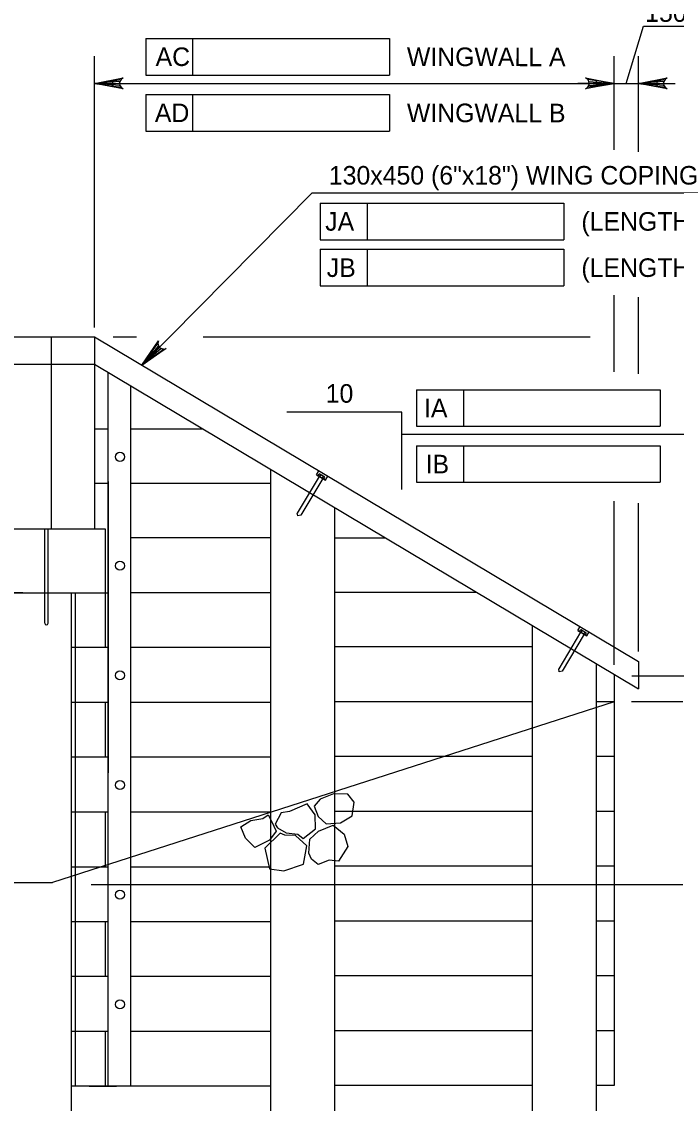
# Model space of a CAD drawing. Extents: x 635440 to 640306, y 296653 to 298484.
# Drawn here: x 638830 to 638935.8, y 296754 to 296928.7 of the extents above; entities that cross this region are included whole.
import ezdxf

# ---------------------------------------------------------------- set-up
doc = ezdxf.new("R2010")
doc.units = 0
doc.layers.add('4', color=7, linetype='Continuous')
doc.layers.add('5', color=7, linetype='Continuous')

# ---------------------------------------------------------------- blocks, each defined once
blk = doc.blocks.new('ROCK')
at = {"layer": '4'}
for points in [[(2.36725, 1.088), (2.2065, 0.82625), (2.378625, 0.506625), (2.66975, 0.3095), (3.128875, 0.403375), (3.48475, 0.6775), (3.4915, 1.123375), (3.25625, 1.36725), (2.783625, 1.308375)], [(1.10175, -0.02725), (1.4015, -0.159125), (1.78825, -0.148875), (1.980875, -0.266), (2.343375, 0.09475), (2.27875, 0.5505), (1.969375, 0.883), (1.4225, 0.553625), (1.152875, 0.479), (1.0105, 0.082)], [(0.74675, 0.359875), (0.882, 0.16), (1.072875, -0.144), (0.892, -0.457375), (0.448125, -0.758625), (0.1, -0.49325), (-0.095, -0.146375), (0.202875, 0.1025), (0.579125, 0.219875)], [(2.231375, -0.71725), (2.2025, -0.266375), (2.45475, 0.037125), (2.9085, 0.28875), (3.2995, 0.047625), (3.46875, -0.344), (3.231625, -0.855), (2.92, -0.860375), (2.5765, -1.054625), (2.340375, -0.904375)], [(1.2085, -0.192875), (0.778375, -0.737625), (1.008375, -1.391375), (1.48725, -1.396875), (2.09825, -1.106625), (2.133375, -0.486375), (1.723125, -0.203375), (1.37425, -0.239875)]]:
    blk.add_lwpolyline(points, close=True, dxfattribs=at)

msp = doc.modelspace()

# ---------------------------------------------------------------- linework, layer by layer
at = {"layer": '4'}
for p, q in [((638812.82, 296877.78), (638841.71, 296877.78)), ((638834.73, 296877.78), (638834.73, 296873.35)), ((638841.71, 296877.78), (638929.64, 296825.35)), ((638841.71, 296877.78), (638841.71, 296873.35)), ((638795.82, 296873.35), (638841.71, 296873.35)), ((638834.73, 296873.35), (638834.73, 296846.77)), ((638841.71, 296873.35), (638929.64, 296820.92)), ((638841.71, 296873.35), (638841.71, 296846.77)), ((638843.96, 296792.52), (638843.96, 296872.01)), ((638847.59, 296793.69), (638847.59, 296869.84)), ((638843.96, 296862.88), (638841.71, 296862.88)), ((638859.28, 296862.88), (638847.59, 296862.88)), ((638870.19, 296856.37), (638870.19, 296799.56)), ((638878.04, 296855.25), (638874.5, 296849.32)), ((638878.61, 296854.91), (638875.07, 296848.98)), ((638877.6, 296855.51), (638877.98, 296856.15)), ((638877.6, 296855.51), (638879.04, 296854.65)), ((638877.87, 296855.35), (638878.02, 296855.61)), ((638878.78, 296854.81), (638877.87, 296855.35)), ((638878.24, 296855.48), (638878.09, 296855.22)), ((638878.18, 296855.63), (638878.87, 296855.22)), ((638878.21, 296855.61), (638878.21, 296855.61)), ((638878.22, 296855.6), (638878.22, 296855.6)), ((638878.23, 296855.6), (638878.23, 296855.6)), ((638878.23, 296855.58), (638878.23, 296855.58)), ((638878.24, 296855.59), (638878.24, 296855.59)), ((638878.24, 296855.57), (638878.24, 296855.57)), ((638878.24, 296855.55), (638878.24, 296855.55)), ((638878.25, 296855.53), (638878.25, 296855.53)), ((638878.25, 296855.51), (638878.25, 296855.51)), ((638878.25, 296855.5), (638878.25, 296855.5)), ((638878.25, 296855.5), (638878.25, 296855.5)), ((638878.26, 296855.58), (638878.26, 296855.58)), ((638878.26, 296855.56), (638878.26, 296855.56)), ((638878.26, 296855.55), (638878.26, 296855.55)), ((638878.27, 296855.57), (638878.27, 296855.57)), ((638878.27, 296855.56), (638878.27, 296855.56)), ((638878.27, 296855.54), (638878.27, 296855.54)), ((638878.27, 296855.52), (638878.27, 296855.52)), ((638878.27, 296855.52), (638878.27, 296855.52)), ((638878.27, 296855.51), (638878.27, 296855.51)), ((638878.27, 296855.49), (638878.27, 296855.49)), ((638878.28, 296855.56), (638878.28, 296855.56)), ((638878.28, 296855.55), (638878.28, 296855.55)), ((638878.28, 296855.55), (638878.28, 296855.55)), ((638878.28, 296855.53), (638878.28, 296855.53)), ((638878.28, 296855.51), (638878.28, 296855.51)), ((638878.28, 296855.5), (638878.28, 296855.5)), ((638878.29, 296855.52), (638878.29, 296855.52)), ((638878.29, 296855.51), (638878.29, 296855.51)), ((638878.29, 296855.49), (638878.29, 296855.49)), ((638878.3, 296855.56), (638878.3, 296855.56)), ((638878.3, 296855.54), (638878.3, 296855.54)), ((638878.31, 296855.55), (638878.31, 296855.55)), ((638878.31, 296855.53), (638878.31, 296855.53)), ((638878.31, 296855.51), (638878.31, 296855.51)), ((638878.31, 296855.5), (638878.31, 296855.5)), ((638878.32, 296855.54), (638878.32, 296855.54)), ((638878.32, 296855.53), (638878.32, 296855.53)), ((638878.32, 296855.51), (638878.32, 296855.51)), ((638878.32, 296855.49), (638878.32, 296855.49)), ((638878.33, 296855.52), (638878.33, 296855.52)), ((638878.33, 296855.5), (638878.33, 296855.5)), ((638878.34, 296855.53), (638878.34, 296855.53)), ((638878.35, 296855.53), (638878.35, 296855.53)), ((638878.35, 296855.51), (638878.35, 296855.51)), ((638878.35, 296855.49), (638878.35, 296855.49)), ((638878.36, 296855.52), (638878.36, 296855.52)), ((638878.36, 296855.5), (638878.36, 296855.5)), ((638878.36, 296855.49), (638878.36, 296855.49)), ((638878.37, 296855.51), (638878.37, 296855.51)), ((638878.37, 296855.49), (638878.37, 296855.49)), ((638878.39, 296855.5), (638878.39, 296855.5)), ((638878.39, 296855.49), (638878.39, 296855.49)), ((638878.4, 296855.5), (638878.4, 296855.5)), ((638878.4, 296855.48), (638878.4, 296855.48)), ((638878.41, 296855.49), (638878.41, 296855.49)), ((638878.42, 296855.48), (638878.42, 296855.48)), ((638878.44, 296855.47), (638878.44, 296855.47)), ((638878.45, 296855.46), (638878.45, 296855.46)), ((638878.46, 296855.46), (638878.46, 296855.46)), ((638878.7, 296855.21), (638878.54, 296854.95)), ((638878.58, 296855.39), (638878.58, 296855.39)), ((638878.59, 296855.38), (638878.59, 296855.38)), ((638878.6, 296855.38), (638878.6, 296855.38)), ((638878.62, 296855.37), (638878.62, 296855.37)), ((638878.63, 296855.36), (638878.63, 296855.36)), ((638878.63, 296855.34), (638878.63, 296855.34)), ((638878.64, 296855.35), (638878.64, 296855.35)), ((638878.64, 296855.34), (638878.64, 296855.34)), ((638878.65, 296855.34), (638878.65, 296855.34)), ((638878.65, 296855.33), (638878.65, 296855.33)), ((638878.65, 296855.31), (638878.65, 296855.31)), ((638878.66, 296855.32), (638878.66, 296855.32)), ((638878.66, 296855.3), (638878.66, 296855.3)), ((638878.67, 296855.34), (638878.67, 296855.34)), ((638878.67, 296855.28), (638878.67, 296855.28)), ((638878.68, 296855.33), (638878.68, 296855.33)), ((638878.68, 296855.31), (638878.68, 296855.31)), ((638878.68, 296855.3), (638878.68, 296855.3)), ((638878.69, 296855.32), (638878.69, 296855.32)), ((638878.69, 296855.3), (638878.69, 296855.3)), ((638878.69, 296855.29), (638878.69, 296855.29)), ((638878.69, 296855.27), (638878.69, 296855.27)), ((638878.69, 296855.26), (638878.69, 296855.26)), ((638878.7, 296855.31), (638878.7, 296855.31)), ((638878.7, 296855.3), (638878.7, 296855.3)), ((638878.7, 296855.28), (638878.7, 296855.28)), ((638878.7, 296855.26), (638878.7, 296855.26)), ((638878.7, 296855.25), (638878.7, 296855.25)), ((638878.7, 296855.23), (638878.7, 296855.23)), ((638878.71, 296855.27), (638878.71, 296855.27)), ((638878.71, 296855.26), (638878.71, 296855.26)), ((638878.71, 296855.24), (638878.71, 296855.24)), ((638878.71, 296855.22), (638878.71, 296855.22)), ((638878.72, 296855.31), (638878.72, 296855.31)), ((638878.72, 296855.29), (638878.72, 296855.29)), ((638878.72, 296855.23), (638878.72, 296855.23)), ((638878.73, 296855.3), (638878.73, 296855.3)), ((638878.73, 296855.28), (638878.73, 296855.28)), ((638878.73, 296855.27), (638878.73, 296855.27)), ((638878.73, 296855.25), (638878.73, 296855.25)), ((638878.74, 296855.29), (638878.74, 296855.29)), ((638878.74, 296855.28), (638878.74, 296855.28)), ((638878.74, 296855.26), (638878.74, 296855.26)), ((638878.74, 296855.24), (638878.74, 296855.24)), ((638878.75, 296855.27), (638878.75, 296855.27)), ((638878.75, 296855.25), (638878.75, 296855.25)), ((638878.76, 296855.28), (638878.76, 296855.28)), ((638878.77, 296855.28), (638878.77, 296855.28)), ((638878.77, 296855.26), (638878.77, 296855.26)), ((638878.77, 296855.24), (638878.77, 296855.24)), ((638878.78, 296855.27), (638878.78, 296855.27)), ((638878.78, 296855.25), (638878.78, 296855.25)), ((638878.78, 296854.81), (638878.94, 296855.07)), ((638878.79, 296855.26), (638878.79, 296855.26)), ((638878.79, 296855.24), (638878.79, 296855.24)), ((638878.81, 296855.25), (638878.81, 296855.25)), ((638878.82, 296855.25), (638878.82, 296855.25)), ((638878.83, 296855.24), (638878.83, 296855.24)), ((638879.04, 296854.65), (638879.42, 296855.29)), ((638843.96, 296854.09), (638841.71, 296854.09)), ((638870.19, 296854.09), (638847.59, 296854.09)), ((638880.53, 296850.21), (638880.53, 296804.3)), ((638874.6, 296848.88), (638874.5, 296849.32)), ((638875.07, 296848.98), (638874.6, 296848.88)), ((638792.85, 296846.77), (638843.44, 296846.77)), ((638833.7, 296831.51), (638833.7, 296846.77)), ((638834.25, 296831.51), (638834.25, 296846.77)), ((638843.44, 296846.77), (638843.44, 296827.58)), ((638870.19, 296845.3), (638847.59, 296845.3)), ((638888.79, 296845.28), (638880.53, 296845.28)), ((638880.53, 296839.01), (638880.53, 296834.32)), ((638794.4, 296836.44), (638843.96, 296836.44)), ((638830.14, 296836.44), (638826.58, 296836.44)), ((638837.99, 296836.44), (638837.99, 296791.02)), ((638838.61, 296836.44), (638838.61, 296756.71)), ((638870.19, 296836.44), (638847.59, 296836.44)), ((638903.53, 296836.49), (638880.53, 296836.49)), ((638912.45, 296831.17), (638912.45, 296814.56)), ((638919.84, 296830.33), (638920.22, 296830.97)), ((638920.11, 296830.17), (638920.27, 296830.43)), ((638920.42, 296830.45), (638921.11, 296830.03)), ((638920.45, 296830.42), (638920.45, 296830.42)), ((638920.46, 296830.42), (638920.46, 296830.42)), ((638920.47, 296830.41), (638920.47, 296830.41)), ((638920.47, 296830.39), (638920.47, 296830.39)), ((638920.48, 296830.37), (638920.48, 296830.37)), ((638920.49, 296830.4), (638920.49, 296830.4)), ((638920.49, 296830.38), (638920.49, 296830.38)), ((638920.5, 296830.39), (638920.5, 296830.39)), ((638920.5, 296830.38), (638920.5, 296830.38)), ((638920.5, 296830.36), (638920.5, 296830.36)), ((638920.51, 296830.39), (638920.51, 296830.39)), ((638920.51, 296830.37), (638920.51, 296830.37)), ((638920.51, 296830.35), (638920.51, 296830.35)), ((638920.52, 296830.38), (638920.52, 296830.38)), ((638920.52, 296830.36), (638920.52, 296830.36)), ((638920.53, 296830.36), (638920.53, 296830.36)), ((638920.54, 296830.37), (638920.54, 296830.37)), ((638920.54, 296830.35), (638920.54, 296830.35)), ((638920.55, 296830.36), (638920.55, 296830.36)), ((638920.57, 296830.36), (638920.57, 296830.36)), ((638920.28, 296830.06), (638916.75, 296824.13)), ((638920.85, 296829.73), (638917.31, 296823.79)), ((638919.84, 296830.33), (638921.28, 296829.47)), ((638921.02, 296829.62), (638920.11, 296830.17)), ((638920.49, 296830.3), (638920.33, 296830.03)), ((638920.49, 296830.33), (638920.49, 296830.33)), ((638920.49, 296830.31), (638920.49, 296830.31)), ((638920.49, 296830.31), (638920.49, 296830.31)), ((638920.5, 296830.34), (638920.5, 296830.34)), ((638920.51, 296830.34), (638920.51, 296830.34)), ((638920.51, 296830.33), (638920.51, 296830.33)), ((638920.51, 296830.32), (638920.51, 296830.32)), ((638920.51, 296830.3), (638920.51, 296830.3)), ((638920.52, 296830.34), (638920.52, 296830.34)), ((638920.52, 296830.33), (638920.52, 296830.33)), ((638920.52, 296830.31), (638920.52, 296830.31)), ((638920.53, 296830.3), (638920.53, 296830.3)), ((638920.54, 296830.34), (638920.54, 296830.34)), ((638920.54, 296830.32), (638920.54, 296830.32)), ((638920.55, 296830.34), (638920.55, 296830.34)), ((638920.55, 296830.33), (638920.55, 296830.33)), ((638920.55, 296830.31), (638920.55, 296830.31)), ((638920.56, 296830.34), (638920.56, 296830.34)), ((638920.56, 296830.32), (638920.56, 296830.32)), ((638920.56, 296830.31), (638920.56, 296830.31)), ((638920.57, 296830.31), (638920.57, 296830.31)), ((638920.58, 296830.35), (638920.58, 296830.35)), ((638920.58, 296830.33), (638920.58, 296830.33)), ((638920.59, 296830.34), (638920.59, 296830.34)), ((638920.59, 296830.32), (638920.59, 296830.32)), ((638920.59, 296830.31), (638920.59, 296830.31)), ((638920.6, 296830.33), (638920.6, 296830.33)), ((638920.6, 296830.32), (638920.6, 296830.32)), ((638920.6, 296830.3), (638920.6, 296830.3)), ((638920.61, 296830.31), (638920.61, 296830.31)), ((638920.62, 296830.32), (638920.62, 296830.32)), ((638920.63, 296830.32), (638920.63, 296830.32)), ((638920.63, 296830.3), (638920.63, 296830.3)), ((638920.64, 296830.31), (638920.64, 296830.31)), ((638920.64, 296830.29), (638920.64, 296830.29)), ((638920.65, 296830.3), (638920.65, 296830.3)), ((638920.67, 296830.29), (638920.67, 296830.29)), ((638920.68, 296830.29), (638920.68, 296830.29)), ((638920.69, 296830.28), (638920.69, 296830.28)), ((638920.71, 296830.27), (638920.71, 296830.27)), ((638920.94, 296830.02), (638920.79, 296829.76)), ((638920.82, 296830.2), (638920.82, 296830.2)), ((638920.83, 296830.2), (638920.83, 296830.2)), ((638920.84, 296830.19), (638920.84, 296830.19)), ((638920.86, 296830.18), (638920.86, 296830.18)), ((638920.87, 296830.17), (638920.87, 296830.17)), ((638920.87, 296830.16), (638920.87, 296830.16)), ((638920.88, 296830.17), (638920.88, 296830.17)), ((638920.88, 296830.15), (638920.88, 296830.15)), ((638920.89, 296830.16), (638920.89, 296830.16)), ((638920.89, 296830.14), (638920.89, 296830.14)), ((638920.89, 296830.12), (638920.89, 296830.12)), ((638920.91, 296830.15), (638920.91, 296830.15)), ((638920.91, 296830.13), (638920.91, 296830.13)), ((638920.91, 296830.12), (638920.91, 296830.12)), ((638920.92, 296830.14), (638920.92, 296830.14)), ((638920.92, 296830.13), (638920.92, 296830.13)), ((638920.92, 296830.11), (638920.92, 296830.11)), ((638920.92, 296830.09), (638920.92, 296830.09)), ((638920.93, 296830.13), (638920.93, 296830.13)), ((638920.93, 296830.12), (638920.93, 296830.12)), ((638920.93, 296830.1), (638920.93, 296830.1)), ((638920.93, 296830.08), (638920.93, 296830.08)), ((638920.93, 296830.07), (638920.93, 296830.07)), ((638920.94, 296830.13), (638920.94, 296830.13)), ((638920.94, 296830.11), (638920.94, 296830.11)), ((638920.94, 296830.09), (638920.94, 296830.09)), ((638920.94, 296830.08), (638920.94, 296830.08)), ((638920.94, 296830.06), (638920.94, 296830.06)), ((638920.94, 296830.04), (638920.94, 296830.04)), ((638920.95, 296830.07), (638920.95, 296830.07)), ((638920.95, 296830.06), (638920.95, 296830.06)), ((638920.95, 296830.04), (638920.95, 296830.04)), ((638920.96, 296830.12), (638920.96, 296830.12)), ((638920.96, 296830.1), (638920.96, 296830.1)), ((638920.96, 296830.09), (638920.96, 296830.09)), ((638920.97, 296830.11), (638920.97, 296830.11)), ((638920.97, 296830.1), (638920.97, 296830.1)), ((638920.97, 296830.08), (638920.97, 296830.08)), ((638920.97, 296830.06), (638920.97, 296830.06)), ((638920.97, 296830.05), (638920.97, 296830.05)), ((638920.98, 296830.11), (638920.98, 296830.11)), ((638920.98, 296830.09), (638920.98, 296830.09)), ((638920.98, 296830.07), (638920.98, 296830.07)), ((638920.98, 296830.06), (638920.98, 296830.06)), ((638920.99, 296830.08), (638920.99, 296830.08)), ((638920.99, 296830.06), (638920.99, 296830.06)), ((638921, 296830.1), (638921, 296830.1)), ((638921.01, 296830.09), (638921.01, 296830.09)), ((638921.01, 296830.07), (638921.01, 296830.07)), ((638921.01, 296830.06), (638921.01, 296830.06)), ((638921.02, 296830.08), (638921.02, 296830.08)), ((638921.02, 296830.07), (638921.02, 296830.07)), ((638921.02, 296829.62), (638921.18, 296829.88)), ((638921.03, 296830.07), (638921.03, 296830.07)), ((638921.03, 296830.06), (638921.03, 296830.06)), ((638921.05, 296830.07), (638921.05, 296830.07)), ((638921.06, 296830.06), (638921.06, 296830.06)), ((638921.07, 296830.05), (638921.07, 296830.05)), ((638921.28, 296829.47), (638921.66, 296830.11)), ((638843.96, 296827.58), (638837.99, 296827.58)), ((638870.19, 296827.58), (638847.59, 296827.58)), ((638912.45, 296827.7), (638880.53, 296827.7)), ((638929.64, 296825.35), (638929.64, 296820.92)), ((638916.84, 296823.69), (638916.75, 296824.13)), ((638917.31, 296823.79), (638916.84, 296823.69)), ((638922.79, 296825.01), (638922.79, 296817.94)), ((638925.74, 296823.25), (638925.74, 296818.84)), ((638925.74, 296818.84), (638834.94, 296789.62)), ((638843.96, 296818.72), (638837.99, 296818.72)), ((638843.44, 296818.72), (638843.44, 296809.86)), ((638870.19, 296818.72), (638847.59, 296818.72)), ((638912.45, 296818.84), (638880.53, 296818.84)), ((638925.74, 296818.84), (638922.79, 296818.84)), ((638925.74, 296818.84), (638925.74, 296756.83)), ((638922.79, 296818), (638922.79, 296745.37)), ((638912.45, 296814.56), (638912.45, 296745.09)), ((638843.96, 296809.86), (638837.99, 296809.86)), ((638870.19, 296809.86), (638847.59, 296809.86)), ((638898.21, 296809.98), (638880.53, 296809.98)), ((638912.45, 296809.98), (638898.21, 296809.98)), ((638925.74, 296809.98), (638922.79, 296809.98)), ((638880.53, 296804.3), (638880.53, 296745.37)), ((638843.96, 296801), (638837.99, 296801)), ((638843.44, 296801), (638843.44, 296792.14)), ((638870.19, 296801), (638847.59, 296801)), ((638912.45, 296801.12), (638880.53, 296801.12)), ((638925.74, 296801.12), (638922.79, 296801.12)), ((638870.19, 296799.56), (638870.19, 296745.09)), ((638847.59, 296756.71), (638847.59, 296793.69)), ((638843.96, 296792.14), (638837.99, 296792.14)), ((638843.96, 296756.71), (638843.96, 296792.52)), ((638870.19, 296792.14), (638847.59, 296792.14)), ((638912.45, 296792.26), (638880.53, 296792.26)), ((638925.74, 296792.26), (638922.79, 296792.26)), ((638837.99, 296791.02), (638837.99, 296745.25)), ((638805.45, 296789.62), (638834.94, 296789.62)), ((638843.96, 296783.28), (638837.99, 296783.28)), ((638843.44, 296783.28), (638843.44, 296774.43)), ((638870.19, 296783.28), (638847.59, 296783.28)), ((638912.45, 296783.41), (638880.53, 296783.41)), ((638925.74, 296783.41), (638922.79, 296783.41)), ((638843.96, 296774.43), (638837.99, 296774.43)), ((638870.19, 296774.43), (638847.59, 296774.43)), ((638912.45, 296774.55), (638880.53, 296774.55)), ((638925.74, 296774.55), (638922.79, 296774.55)), ((638912.45, 296765.69), (638880.53, 296765.69)), ((638925.74, 296765.69), (638922.79, 296765.69)), ((638843.96, 296765.57), (638837.99, 296765.57)), ((638843.44, 296765.57), (638843.44, 296756.71)), ((638870.19, 296765.57), (638847.59, 296765.57)), ((638870.19, 296756.71), (638837.99, 296756.71)), ((638840.87, 296756.71), (638845.3, 296756.71)), ((638912.45, 296756.83), (638880.53, 296756.83)), ((638925.74, 296756.83), (638922.79, 296756.83))]:
    msp.add_line(p, q, dxfattribs=at)
for centre in [(638845.85, 296858.41), (638845.85, 296840.82), (638845.85, 296823.1), (638845.85, 296805.38), (638845.85, 296787.66), (638845.85, 296769.95)]:
    msp.add_circle(centre, 0.738, dxfattribs=at)
for centre, radius, start, end in [((638878.11, 296855.51), 0.135, 346.6464, 131.7428), ((638878.3, 296855.06), 0.424, 20.2446, 98.1446), ((638878.79, 296855.09), 0.148, 61.0217, 127.9076), ((638878.79, 296855.09), 0.148, 350.4815, 61.0216), ((638833.97, 296831.55), 0.28, 188.6735, 351.3265), ((638920.35, 296830.33), 0.135, 346.6464, 131.7428), ((638920.55, 296829.88), 0.424, 20.2446, 98.1446), ((638921.03, 296829.91), 0.148, 61.0217, 127.9076), ((638921.03, 296829.91), 0.148, 350.4815, 61.0216)]:
    msp.add_arc(centre, radius, start, end, dxfattribs=at)
at = {"layer": '5'}
for p, q in [((638927.67, 296918.73), (638930.43, 296927.96)), ((638930.43, 296927.96), (638952.38, 296927.96)), ((638850.03, 296926), (638850.03, 296920.09)), ((638850.03, 296926), (638889.4, 296926)), ((638857.59, 296926), (638857.59, 296920.09)), ((638889.4, 296926), (638889.4, 296920.09)), ((638841.71, 296879.31), (638841.71, 296923.16)), ((638925.74, 296907.99), (638925.74, 296923.16)), ((638929.64, 296907.66), (638929.64, 296923.16)), ((638850.03, 296920.09), (638889.4, 296920.09)), ((638841.71, 296918.73), (638925.74, 296918.73)), ((638922.79, 296918.73), (638919.84, 296918.73)), ((638925.74, 296918.73), (638933.54, 296918.73)), ((638929.64, 296918.73), (638935.55, 296918.73)), ((638850.03, 296916.94), (638889.4, 296916.94)), ((638850.03, 296916.94), (638850.03, 296911.03)), ((638857.59, 296916.94), (638857.59, 296911.03)), ((638889.4, 296916.94), (638889.4, 296911.03)), ((638850.03, 296911.03), (638889.4, 296911.03)), ((638849.41, 296873.19), (638876.92, 296901.05)), ((638876.92, 296901.05), (638970.61, 296901.05)), ((638878.23, 296899.39), (638878.23, 296893.49)), ((638878.23, 296899.39), (638917.6, 296899.39)), ((638885.79, 296899.39), (638885.79, 296893.49)), ((638917.6, 296899.39), (638917.6, 296893.49)), ((638878.23, 296893.49), (638917.6, 296893.49)), ((638878.23, 296891.93), (638917.6, 296891.93)), ((638878.23, 296891.93), (638878.23, 296886.02)), ((638885.79, 296891.93), (638885.79, 296886.02)), ((638917.6, 296891.93), (638917.6, 296886.02)), ((638878.23, 296886.02), (638917.6, 296886.02)), ((638925.74, 296872.12), (638925.74, 296884.51)), ((638929.64, 296871.79), (638929.64, 296884.18)), ((638844.76, 296877.78), (638848.51, 296877.78)), ((638859.28, 296877.78), (638921.82, 296877.78)), ((638893.77, 296869.25), (638933.15, 296869.25)), ((638893.77, 296869.25), (638893.77, 296863.35)), ((638901.34, 296869.25), (638901.34, 296863.35)), ((638933.15, 296869.25), (638933.15, 296863.35)), ((638891.42, 296865.64), (638872.84, 296865.64)), ((638891.42, 296853.11), (638891.42, 296865.64)), ((638966.27, 296861.99), (638891.42, 296861.99)), ((638893.77, 296863.35), (638933.15, 296863.35)), ((638893.77, 296860.19), (638893.77, 296854.29)), ((638893.77, 296860.19), (638933.15, 296860.19)), ((638901.34, 296860.19), (638901.34, 296854.29)), ((638933.15, 296860.19), (638933.15, 296854.29)), ((638843.96, 296854.42), (638843.96, 296807.34)), ((638893.77, 296854.29), (638933.15, 296854.29)), ((638925.74, 296824.78), (638925.74, 296851.25)), ((638929.64, 296826.94), (638929.64, 296850.92)), ((638928.57, 296823.03), (639030.02, 296823.03)), ((638936.79, 296818.84), (638928.51, 296818.84)), ((638936.79, 296789.26), (638841.21, 296789.26))]:
    msp.add_line(p, q, dxfattribs=at)
for points in [[(638841.71, 296918.73), (638846.37, 296919.61), (638846.02, 296919.36), (638845.83, 296919.05), (638845.78, 296918.73), (638845.83, 296918.42), (638846.02, 296918.11), (638846.37, 296917.86), (638841.71, 296918.73), (638846.02, 296918.11), (638845.83, 296918.42), (638841.71, 296918.73), (638845.78, 296918.73), (638845.83, 296919.05), (638841.71, 296918.73), (638846.02, 296919.36)], [(638925.74, 296918.73), (638921.08, 296917.86), (638921.44, 296918.11), (638921.62, 296918.42), (638921.68, 296918.73), (638921.62, 296919.05), (638921.44, 296919.36), (638921.08, 296919.61), (638925.74, 296918.73), (638921.44, 296919.36), (638921.62, 296919.05), (638925.74, 296918.73), (638921.68, 296918.73), (638921.62, 296918.42), (638925.74, 296918.73), (638921.44, 296918.11)], [(638929.64, 296918.73), (638934.3, 296919.61), (638933.94, 296919.36), (638933.76, 296919.05), (638933.7, 296918.73), (638933.76, 296918.42), (638933.94, 296918.11), (638934.3, 296917.86), (638929.64, 296918.73), (638933.94, 296918.11), (638933.76, 296918.42), (638929.64, 296918.73), (638933.7, 296918.73), (638933.76, 296919.05), (638929.64, 296918.73), (638933.94, 296919.36)], [(638849.41, 296873.19), (638852.06, 296877.12), (638851.99, 296876.69), (638852.08, 296876.34), (638852.26, 296876.08), (638852.52, 296875.9), (638852.87, 296875.81), (638853.3, 296875.89), (638849.41, 296873.19), (638852.87, 296875.81), (638852.52, 296875.9), (638849.41, 296873.19), (638852.26, 296876.08), (638852.08, 296876.34), (638849.41, 296873.19), (638851.99, 296876.69)]]:
    msp.add_lwpolyline(points, dxfattribs=at)
for points in [[(638844.67, 296919.23), (638844.67, 296918.24), (638841.71, 296918.73)], [(638922.79, 296919.23), (638922.79, 296918.24), (638925.74, 296918.73)], [(638932.59, 296919.23), (638932.59, 296918.24), (638929.64, 296918.73)], [(638851.74, 296874.87), (638851.06, 296875.54), (638849.41, 296873.19)]]:
    msp.add_lwpolyline(points, close=True, dxfattribs=at)

# ---------------------------------------------------------------- block references
at = {"layer": '5', "xscale": 4.921475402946, "yscale": 4.921475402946, "rotation": -7.300632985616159}
msp.add_blockref('ROCK', (638865.95, 296799.29), dxfattribs=at)

# ---------------------------------------------------------------- texts
at = {"layer": '5'}
for s, height, p in [('150 (6")', 3, (638930.73, 296928.68)), ('130x450 (6"x18") WING COPING', 3.0001, (638879.61, 296902.39)), ('JA', 3, (638879.02, 296894.94)), ('(LENGTH) WINGWALL A', 3.0001, (638920.42, 296894.94)), ('JB', 3, (638879.27, 296887.47)), ('(LENGTH) WINGWALL B', 3.0001, (638920.42, 296887.47)), ('10', 3, (638879.1, 296867.15))]:
    msp.add_text(s, height=height, dxfattribs=at).set_placement(p)
for s, p in [('AC', (638851.61, 296921.55)), ('WINGWALL A', (638892.22, 296921.54)), ('AD', (638851.49, 296912.49)), ('WINGWALL B', (638892.22, 296912.48)), ('IA', (638894.99, 296864.8)), ('IB', (638895.24, 296855.74))]:
    msp.add_text(s, height=3, rotation=359.9382, dxfattribs=at).set_placement(p)

doc.saveas('drawing.dxf')
